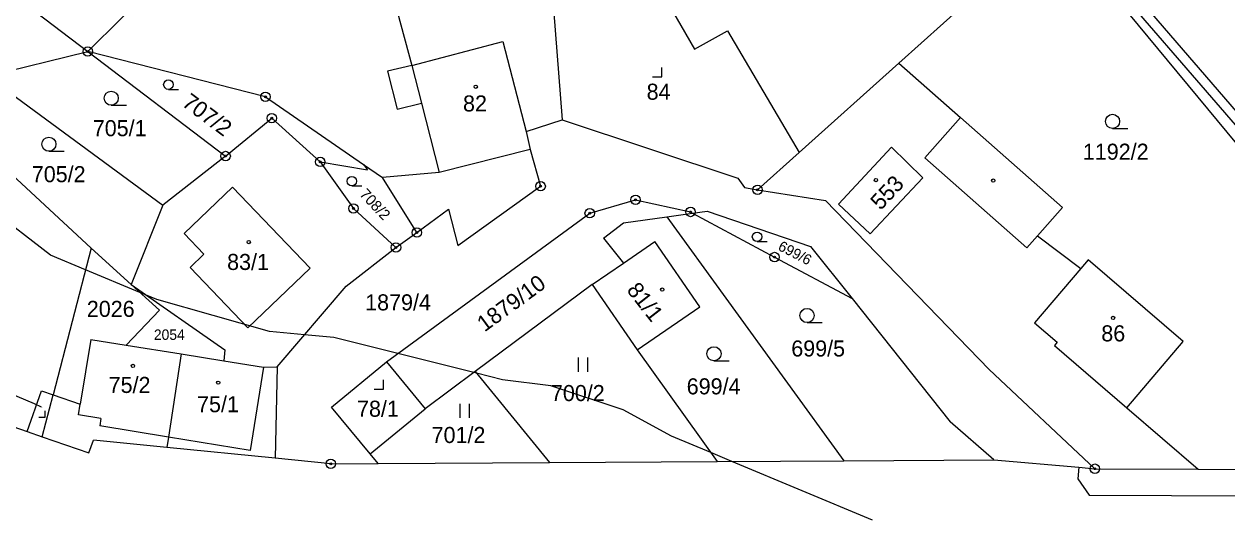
# Model space of a CAD drawing. Extents: x -445050 to -440454, y -1134563 to -1129741.
# Drawn here: x -441645.7 to -441518.4, y -1131833.5 to -1131781 of the extents above; entities that cross this region are included whole.
import ezdxf

# ---------------------------------------------------------------- set-up
doc = ezdxf.new("R2010")
doc.units = 0
for name, color, linetype in [('Vrstva 1', 7, 'Continuous'), ('Vrstva 16', 7, 'Continuous'), ('Vrstva 18', 7, 'Continuous'), ('Vrstva 19', 7, 'Continuous'), ('Vrstva 24', 7, 'Continuous'), ('Vrstva 25', 7, 'Continuous'), ('Vrstva 3', 7, 'Continuous'), ('Vrstva 30', 7, 'Continuous'), ('Vrstva 37', 7, 'Continuous'), ('Vrstva 4', 7, 'Continuous'), ('Vrstva 52', 7, 'Continuous')]:
    doc.layers.add(name, color=color, linetype=linetype)

msp = doc.modelspace()

# ---------------------------------------------------------------- linework, layer by layer
at = {"layer": 'Vrstva 1'}
for p, q in [((-441585.84, -1131801.04), (-441580.99, -1131799.62)), ((-441580.99, -1131799.62), (-441575.17, -1131800.91)), ((-441607.33, -1131816.79), (-441585.84, -1131801.04)), ((-441577.68, -1131801.41), (-441574.95, -1131801.03)), ((-441575.17, -1131800.91), (-441574.95, -1131801.03)), ((-441574.95, -1131801.03), (-441573.4, -1131800.81)), ((-441574.95, -1131801.03), (-441566.29, -1131805.68)), ((-441562.48, -1131804.56), (-441558.09, -1131810.08)), ((-441566.29, -1131805.68), (-441558.09, -1131810.08)), ((-441634.34, -1131808.58), (-441624.44, -1131815.5)), ((-441558.09, -1131810.08), (-441547.73, -1131823.13)), ((-441624.44, -1131815.5), (-441624.54, -1131816.66)), ((-441629.04, -1131815.92), (-441624.54, -1131816.66)), ((-441624.54, -1131816.66), (-441620.36, -1131817.34)), ((-441543.1, -1131827.15), (-441534.12, -1131827.94)), ((-441534.12, -1131827.94), (-441534.22, -1131829.15)), ((-441534.12, -1131827.94), (-441532.41, -1131828.09)), ((-441534.22, -1131829.15), (-441533.03, -1131830.89)), ((-441533.03, -1131830.89), (-441505.8, -1131830.99))]:
    msp.add_line(p, q, dxfattribs=at)
for points in [[(-441677.25, -1131754.76), (-441638.93, -1131783.92)], [(-441553.13, -1131785.14), (-441536.6, -1131770.31)], [(-441638.93, -1131783.92), (-441628.24, -1131773.3)], [(-441531.07, -1131777.19), (-441508.89, -1131803.99)], [(-441577.63, -1131778.66), (-441574.76, -1131783.67)], [(-441606.16, -1131779.78), (-441604.66, -1131785.41)], [(-441589.68, -1131779.41), (-441588.74, -1131791.17)], [(-441574.76, -1131783.67), (-441571.27, -1131781.72)], [(-441571.27, -1131781.72), (-441563.68, -1131794.61)], [(-441649.56, -1131786.53), (-441638.93, -1131783.92)], [(-441638.93, -1131783.92), (-441624.35, -1131794.99)], [(-441620.14, -1131788.71), (-441638.93, -1131783.92)], [(-441604.66, -1131785.41), (-441607.22, -1131786.02)], [(-441607.22, -1131786.02), (-441606.19, -1131790.03)], [(-441563.68, -1131794.61), (-441553.13, -1131785.14)], [(-441553.13, -1131785.14), (-441546.61, -1131790.91)], [(-441649.56, -1131786.53), (-441630.98, -1131800.19)], [(-441656.28, -1131788.34), (-441638.56, -1131804.73)], [(-441620.14, -1131788.71), (-441609.78, -1131795.87)], [(-441606.19, -1131790.03), (-441603.64, -1131789.38)], [(-441603.64, -1131789.38), (-441601.75, -1131796.73)], [(-441624.35, -1131794.99), (-441619.47, -1131790.98)], [(-441619.47, -1131790.98), (-441614.34, -1131795.61)], [(-441592.57, -1131792.38), (-441588.74, -1131791.17)], [(-441588.74, -1131791.17), (-441570.18, -1131797.32)], [(-441546.61, -1131790.91), (-441535.83, -1131800.45)], [(-441592.57, -1131792.38), (-441592.12, -1131794.29)], [(-441624.35, -1131794.99), (-441630.98, -1131800.19)], [(-441592.12, -1131794.29), (-441591.03, -1131798.19)], [(-441568.09, -1131798.56), (-441563.68, -1131794.61)], [(-441553.91, -1131794.05), (-441559.54, -1131800.07)], [(-441550.6, -1131797.28), (-441553.91, -1131794.05)], [(-441614.34, -1131795.61), (-441609.36, -1131796.45)], [(-441614.34, -1131795.61), (-441610.83, -1131800.54)], [(-441609.78, -1131795.87), (-441609.36, -1131796.45)], [(-441609.78, -1131795.87), (-441607.76, -1131797.27)], [(-441601.75, -1131796.73), (-441607.76, -1131797.27)], [(-441604.12, -1131803.09), (-441607.76, -1131797.27)], [(-441570.18, -1131797.32), (-441569.48, -1131798.32)], [(-441556.16, -1131803.22), (-441550.6, -1131797.28)], [(-441599.8, -1131804.47), (-441591.03, -1131798.19)], [(-441569.48, -1131798.32), (-441568.09, -1131798.56)], [(-441568.09, -1131798.56), (-441560.89, -1131799.68)], [(-441630.98, -1131800.19), (-441634.34, -1131808.58)], [(-441560.89, -1131799.68), (-441543.6, -1131817.59)], [(-441559.54, -1131800.07), (-441556.16, -1131803.22)], [(-441610.83, -1131800.54), (-441606.33, -1131804.66)], [(-441604.12, -1131803.09), (-441600.78, -1131800.61)], [(-441600.78, -1131800.61), (-441599.8, -1131804.47)], [(-441582.26, -1131802.06), (-441577.68, -1131801.41)], [(-441577.68, -1131801.41), (-441558.96, -1131827.24)], [(-441573.4, -1131800.81), (-441562.48, -1131804.56)], [(-441535.83, -1131800.45), (-441538.46, -1131803.43)], [(-441584.37, -1131803.69), (-441582.26, -1131802.06)], [(-441606.33, -1131804.66), (-441604.12, -1131803.09)], [(-441584.37, -1131803.69), (-441582.25, -1131806.33)], [(-441582.25, -1131806.33), (-441578.94, -1131804.05)], [(-441574.18, -1131810.97), (-441578.94, -1131804.05)], [(-441538.46, -1131803.43), (-441533.88, -1131806.89)], [(-441638.56, -1131804.73), (-441642.59, -1131820.28)], [(-441638.56, -1131804.73), (-441634.34, -1131808.58)], [(-441611.59, -1131808.75), (-441606.33, -1131804.66)], [(-441585.57, -1131808.6), (-441582.25, -1131806.33)], [(-441533.11, -1131805.99), (-441533.88, -1131806.89)], [(-441523.06, -1131814.62), (-441533.11, -1131805.99)], [(-441634.34, -1131808.58), (-441631.36, -1131811.31)], [(-441618.89, -1131817.29), (-441611.59, -1131808.75)], [(-441585.57, -1131808.6), (-441597.96, -1131817.81)], [(-441585.57, -1131808.6), (-441580.81, -1131815.52)], [(-441631.36, -1131811.31), (-441634.88, -1131815)], [(-441580.81, -1131815.52), (-441574.18, -1131810.97)], [(-441638.6, -1131814.41), (-441639.73, -1131821.27)], [(-441638.6, -1131814.41), (-441634.88, -1131815)], [(-441634.88, -1131815), (-441629.04, -1131815.92)], [(-441580.81, -1131815.52), (-441572.35, -1131827.32)], [(-441529.03, -1131821.64), (-441523.06, -1131814.62)], [(-441629.04, -1131815.92), (-441630.38, -1131824.74)], [(-441613.14, -1131821.56), (-441607.33, -1131816.79)], [(-441607.33, -1131816.79), (-441603.26, -1131821.75)], [(-441620.36, -1131817.34), (-441618.89, -1131817.29)], [(-441618.89, -1131817.29), (-441619.1, -1131826.98)], [(-441597.96, -1131817.81), (-441603.26, -1131821.75)], [(-441597.96, -1131817.81), (-441590.1, -1131827.43)], [(-441543.6, -1131817.59), (-441532.41, -1131828.09)], [(-441661.38, -1131818.56), (-441645.34, -1131824.15)], [(-441645.34, -1131824.15), (-441643.84, -1131819.84)], [(-441643.84, -1131819.84), (-441642.59, -1131820.28)], [(-441643.74, -1131824.7), (-441642.59, -1131820.28)], [(-441642.59, -1131820.28), (-441639.73, -1131821.27)], [(-441609.07, -1131826.52), (-441613.14, -1131821.56)], [(-441609.07, -1131826.52), (-441603.26, -1131821.75)], [(-441529.03, -1131821.64), (-441521.5, -1131828.12)], [(-441543.1, -1131827.15), (-441547.73, -1131823.13)], [(-441645.34, -1131824.15), (-441643.74, -1131824.7)], [(-441643.74, -1131824.7), (-441638.81, -1131826.42)], [(-441638.81, -1131826.42), (-441638.33, -1131825.05)], [(-441630.56, -1131825.83), (-441638.33, -1131825.05)], [(-441630.38, -1131824.74), (-441630.56, -1131825.83)], [(-441619.1, -1131826.98), (-441630.56, -1131825.83)], [(-441613.23, -1131827.57), (-441619.1, -1131826.98)], [(-441608.23, -1131827.54), (-441609.07, -1131826.52)], [(-441613.23, -1131827.57), (-441608.23, -1131827.54)], [(-441608.23, -1131827.54), (-441590.1, -1131827.43)], [(-441590.1, -1131827.43), (-441572.35, -1131827.32)], [(-441572.35, -1131827.32), (-441558.96, -1131827.24)], [(-441558.96, -1131827.24), (-441543.1, -1131827.15)], [(-441532.41, -1131828.09), (-441521.5, -1131828.12)], [(-441521.5, -1131828.12), (-441489.45, -1131828.2)]]:
    msp.add_lwpolyline(points, dxfattribs=at)
at = {"layer": 'Vrstva 16'}
msp.add_line((-441644.57, -1131821.23), (-441647.33, -1131820.06), dxfattribs=at)
msp.add_lwpolyline([(-441643.82, -1131821.56), (-441644.57, -1131821.23)], dxfattribs=at)
at = {"layer": 'Vrstva 24'}
for centre, radius in [((-441638.93, -1131783.92), 0.5), ((-441638.93, -1131783.92), 0.1), ((-441620.14, -1131788.71), 0.5), ((-441620.14, -1131788.71), 0.1), ((-441619.47, -1131790.98), 0.5), ((-441619.47, -1131790.98), 0.1), ((-441624.35, -1131794.99), 0.5), ((-441624.35, -1131794.99), 0.1), ((-441614.34, -1131795.61), 0.5), ((-441614.34, -1131795.61), 0.1), ((-441591.03, -1131798.19), 0.5), ((-441591.03, -1131798.19), 0.1), ((-441568.09, -1131798.56), 0.5), ((-441568.09, -1131798.56), 0.1), ((-441610.83, -1131800.54), 0.5), ((-441580.99, -1131799.62), 0.5), ((-441580.99, -1131799.62), 0.1), ((-441610.83, -1131800.54), 0.1), ((-441585.84, -1131801.04), 0.5), ((-441585.84, -1131801.04), 0.1), ((-441575.17, -1131800.91), 0.5), ((-441575.17, -1131800.91), 0.1), ((-441604.12, -1131803.09), 0.5), ((-441606.33, -1131804.66), 0.5), ((-441604.12, -1131803.09), 0.1), ((-441606.33, -1131804.66), 0.1), ((-441566.29, -1131805.68), 0.5), ((-441566.29, -1131805.68), 0.1), ((-441613.23, -1131827.57), 0.5), ((-441613.23, -1131827.57), 0.1), ((-441532.41, -1131828.09), 0.5), ((-441532.41, -1131828.09), 0.1)]:
    msp.add_circle(centre, radius, dxfattribs=at)
at = {"layer": 'Vrstva 25'}
for p, q in [((-441630.4, -1131787.93), (-441629.33, -1131787.93)), ((-441636.45, -1131789.62), (-441634.85, -1131789.62)), ((-441530.54, -1131792.07), (-441528.94, -1131792.07)), ((-441643.04, -1131794.49), (-441641.44, -1131794.49)), ((-441611, -1131798.15), (-441609.93, -1131798.15)), ((-441568.14, -1131804.04), (-441567.07, -1131804.04)), ((-441562.85, -1131812.62), (-441561.25, -1131812.62)), ((-441587.04, -1131817.82), (-441587.04, -1131816.32)), ((-441586.04, -1131817.82), (-441586.04, -1131816.32)), ((-441572.7, -1131816.67), (-441571.1, -1131816.67)), ((-441599.55, -1131822.71), (-441599.55, -1131821.21)), ((-441598.55, -1131822.71), (-441598.55, -1131821.21))]:
    msp.add_line(p, q, dxfattribs=at)
for points in [[(-441579.21, -1131786.62), (-441578.21, -1131786.62), (-441578.21, -1131785.62)], [(-441608.64, -1131819.67), (-441607.64, -1131819.67), (-441607.64, -1131818.67)], [(-441644.12, -1131822.62), (-441643.45, -1131822.62), (-441643.45, -1131821.95)]]:
    msp.add_lwpolyline(points, dxfattribs=at)
for centre, radius in [((-441630.4, -1131787.43), 0.503), ((-441597.9, -1131787.66), 0.175), ((-441636.45, -1131788.87), 0.75), ((-441530.54, -1131791.32), 0.75), ((-441643.04, -1131793.74), 0.75), ((-441611, -1131797.65), 0.503), ((-441555.57, -1131797.53), 0.175), ((-441543.16, -1131797.59), 0.175), ((-441621.9, -1131804.1), 0.175), ((-441568.14, -1131803.54), 0.503), ((-441578.17, -1131809.12), 0.175), ((-441562.85, -1131811.87), 0.75), ((-441530.48, -1131812.13), 0.175), ((-441572.7, -1131815.92), 0.75), ((-441634.15, -1131817.2), 0.175), ((-441625.13, -1131818.98), 0.175)]:
    msp.add_circle(centre, radius, dxfattribs=at)
at = {"layer": 'Vrstva 3'}
for points in [[(-441604.66, -1131785.41), (-441595.02, -1131782.88)], [(-441595.02, -1131782.88), (-441592.57, -1131792.38)], [(-441604.66, -1131785.41), (-441603.64, -1131789.38)], [(-441603.64, -1131789.38), (-441601.75, -1131796.73)], [(-441592.57, -1131792.38), (-441592.12, -1131794.29)], [(-441592.12, -1131794.29), (-441601.75, -1131796.73)], [(-441553.91, -1131794.05), (-441559.54, -1131800.07)], [(-441550.6, -1131797.28), (-441553.91, -1131794.05)], [(-441556.16, -1131803.22), (-441550.6, -1131797.28)], [(-441628.74, -1131803.2), (-441623.61, -1131798.29)], [(-441623.61, -1131798.29), (-441615.41, -1131806.86)], [(-441559.54, -1131800.07), (-441556.16, -1131803.22)], [(-441626.64, -1131805.39), (-441628.74, -1131803.2)], [(-441582.25, -1131806.33), (-441578.94, -1131804.05)], [(-441574.18, -1131810.97), (-441578.94, -1131804.05)], [(-441628.1, -1131806.8), (-441626.64, -1131805.39)], [(-441585.57, -1131808.6), (-441582.25, -1131806.33)], [(-441533.11, -1131805.99), (-441533.88, -1131806.89)], [(-441523.06, -1131814.62), (-441533.11, -1131805.99)], [(-441622, -1131813.17), (-441628.1, -1131806.8)], [(-441622, -1131813.17), (-441615.41, -1131806.86)], [(-441533.88, -1131806.89), (-441538.81, -1131812.63)], [(-441585.57, -1131808.6), (-441580.81, -1131815.52)], [(-441580.81, -1131815.52), (-441574.18, -1131810.97)], [(-441538.81, -1131812.63), (-441536.38, -1131814.71)], [(-441638.6, -1131814.41), (-441639.73, -1131821.27)], [(-441638.6, -1131814.41), (-441634.88, -1131815)], [(-441634.88, -1131815), (-441629.04, -1131815.92)], [(-441536.38, -1131814.71), (-441536.68, -1131815.06)], [(-441536.68, -1131815.06), (-441529.03, -1131821.64)], [(-441529.03, -1131821.64), (-441523.06, -1131814.62)], [(-441629.04, -1131815.92), (-441630.38, -1131824.74)], [(-441629.04, -1131815.92), (-441630.38, -1131824.74)], [(-441629.04, -1131815.92), (-441624.54, -1131816.66)], [(-441624.54, -1131816.66), (-441620.36, -1131817.34)], [(-441620.36, -1131817.34), (-441621.76, -1131826.16)], [(-441639.91, -1131822.39), (-441639.73, -1131821.27)], [(-441637.54, -1131822.77), (-441639.91, -1131822.39)], [(-441637.54, -1131822.77), (-441637.67, -1131823.56)], [(-441630.38, -1131824.74), (-441637.67, -1131823.56)], [(-441621.76, -1131826.16), (-441630.38, -1131824.74)]]:
    msp.add_lwpolyline(points, dxfattribs=at)
at = {"layer": 'Vrstva 30'}
msp.add_lwpolyline([(-441536.6, -1131770.31), (-441540.7, -1131765.2), (-441539.9, -1131764.56), (-441536.62, -1131768.67), (-441531.55, -1131773.9), (-441516.78, -1131791.04), (-441509.15, -1131800.59), (-441509.36, -1131803.43), (-441510.28, -1131802.32), (-441510.17, -1131800.91), (-441517.54, -1131791.68), (-441532.29, -1131774.58), (-441536.6, -1131770.31)], dxfattribs=at)
at = {"layer": 'Vrstva 37'}
for centre in [(-441597.9, -1131787.66), (-441555.57, -1131797.53), (-441621.9, -1131804.1), (-441578.17, -1131809.12), (-441530.48, -1131812.13), (-441634.15, -1131817.2), (-441625.13, -1131818.98)]:
    msp.add_circle(centre, 0.175, dxfattribs=at)
at = {"layer": 'Vrstva 4'}
for points in [[(-441604.66, -1131785.41), (-441595.02, -1131782.88)], [(-441595.02, -1131782.88), (-441592.57, -1131792.38)], [(-441604.66, -1131785.41), (-441603.64, -1131789.38)], [(-441550.39, -1131795.18), (-441546.61, -1131790.91)], [(-441592.12, -1131794.29), (-441601.75, -1131796.73)], [(-441539.6, -1131804.72), (-441550.39, -1131795.18)], [(-441628.74, -1131803.2), (-441623.61, -1131798.29)], [(-441623.61, -1131798.29), (-441615.41, -1131806.86)], [(-441626.64, -1131805.39), (-441628.74, -1131803.2)], [(-441538.46, -1131803.43), (-441539.6, -1131804.72)], [(-441628.1, -1131806.8), (-441626.64, -1131805.39)], [(-441622, -1131813.17), (-441628.1, -1131806.8)], [(-441622, -1131813.17), (-441615.41, -1131806.86)], [(-441533.88, -1131806.89), (-441538.81, -1131812.63)], [(-441538.81, -1131812.63), (-441536.38, -1131814.71)], [(-441536.38, -1131814.71), (-441536.68, -1131815.06)], [(-441536.68, -1131815.06), (-441529.03, -1131821.64)], [(-441620.36, -1131817.34), (-441621.76, -1131826.16)], [(-441639.91, -1131822.39), (-441639.73, -1131821.27)], [(-441637.54, -1131822.77), (-441639.91, -1131822.39)], [(-441637.54, -1131822.77), (-441637.67, -1131823.56)], [(-441630.38, -1131824.74), (-441637.67, -1131823.56)], [(-441621.76, -1131826.16), (-441630.38, -1131824.74)]]:
    msp.add_lwpolyline(points, dxfattribs=at)
at = {"layer": 'Vrstva 52'}
msp.add_lwpolyline([(-441555.93, -1131833.55), (-441570.8, -1131827.31), (-441573.03, -1131826.37), (-441577.19, -1131824.63), (-441582.3, -1131821.86), (-441589.95, -1131819.31), (-441595.05, -1131818.67), (-441597.82, -1131817.98), (-441598.1, -1131817.91), (-441612.91, -1131814.21), (-441616.01, -1131813.92), (-441619.71, -1131813.57), (-441631.62, -1131810.17), (-441633.43, -1131809.42), (-441639.16, -1131807.04), (-441642.88, -1131805.49), (-441649.29, -1131800.54)], dxfattribs=at)

# ---------------------------------------------------------------- texts
at = {"layer": 'Vrstva 18'}
for s, height, rotation, p in [('707/2', 1.7, 323.0529, (-441629.07, -1131789.58)), ('708/2', 1.14, 313.1979, (-441610.26, -1131799.1)), ('699/6', 1.1, 332.6797, (-441566.01, -1131804.89)), ('1879/10', 1.7, 36.2377, (-441596.96, -1131813.67))]:
    msp.add_text(s, height=height, rotation=rotation, dxfattribs=at).set_placement(p)
for s, height, p in [('705/1', 1.7, (-441638.4, -1131792.89)), ('1192/2', 1.7, (-441533.68, -1131795.38)), ('705/2', 1.7, (-441644.85, -1131797.76)), ('2026', 1.7, (-441639.03, -1131812.02)), ('1879/4', 1.7, (-441609.59, -1131811.33)), ('2054', 1.1, (-441631.94, -1131814.45)), ('699/5', 1.7, (-441564.52, -1131816.21)), ('700/2', 1.7, (-441589.94, -1131820.93)), ('699/4', 1.7, (-441575.58, -1131820.22)), ('701/2', 1.7, (-441602.56, -1131825.37))]:
    msp.add_text(s, height=height, dxfattribs=at).set_placement(p)
at = {"layer": 'Vrstva 19'}
for s, height, p in [('84', 1.7, (-441579.82, -1131789.03)), ('82', 1.7, (-441599.24, -1131790.27)), ('83/1', 1.7, (-441624.19, -1131807.05)), ('86', 1.7, (-441531.73, -1131814.61)), ('75/2', 1.7, (-441636.72, -1131820.07)), ('75/1', 1.7, (-441627.37, -1131822.11)), ('73', 0.1, (-441643.83, -1131821.61)), ('78/1', 1.7, (-441610.45, -1131822.59))]:
    msp.add_text(s, height=height, dxfattribs=at).set_placement(p)
for s, rotation, p in [('553', 46.9377, (-441555.07, -1131800.81)), ('81/1', 307.9242, (-441582, -1131809.2))]:
    msp.add_text(s, height=1.7, rotation=rotation, dxfattribs=at).set_placement(p)

doc.saveas('drawing.dxf')
